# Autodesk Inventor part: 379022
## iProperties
Created: 2006-05
Part Number: 379022
Document SubType Name: Modeling
Designer: I.Baliuc
Material: Nylon  6
Description: Griffmutter
Density: 1.13 g/cm^3
Title: Griffmutter
Abmessung: M6
Author: T.Messerschmitt
Revision Number: 379022
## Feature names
1. Basis1
2. Bohrung_M6 [Hole]
